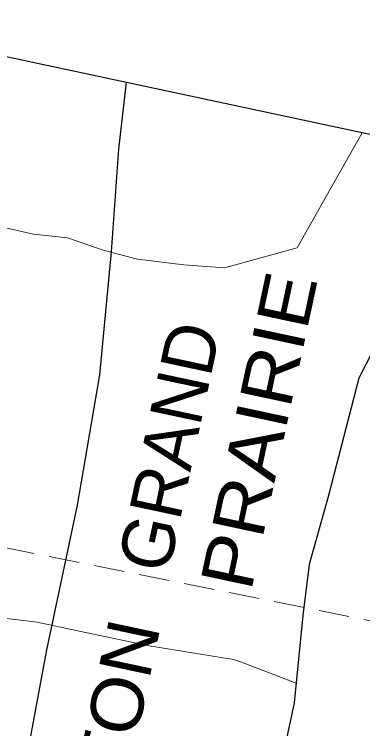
# Model space of a CAD drawing. Extents: x 2363411 to 2369126, y 6976878 to 6988319.
# Drawn here: x 2365979.2 to 2366047.6, y 6977238.8 to 6977379 of the extents above; entities that cross this region are included whole.
import ezdxf

# ---------------------------------------------------------------- set-up
doc = ezdxf.new("R2010")
doc.units = 0
doc.header["$LTSCALE"] = 2
doc.linetypes.add('MEDIUM_DASHED', pattern=[4.5, 3, -1.5])
doc.layers.add('62', color=7, linetype='Continuous', lineweight=13)
doc.layers.add('63', color=7, linetype='Continuous', lineweight=13)

msp = doc.modelspace()

# ---------------------------------------------------------------- linework, layer by layer
at = {"layer": '62', "linetype": 'MEDIUM_DASHED'}
msp.add_line((2365844.834, 6977300.827), (2366120.392, 6977245.768), dxfattribs=at)
at = {"layer": '62'}
for p, q in [((2365983.687, 6977259.747), (2365971.313, 6977261.17)), ((2366022.198, 6977252.394), (2366023.784, 6977251.848)), ((2366023.784, 6977251.848), (2366034.504, 6977247.738))]:
    msp.add_line(p, q, dxfattribs=at)
at = {"layer": '62', "lineweight": 25}
for points in [[(2365678.211, 6976974.92), (2366133.213, 6976877.7), (2366227.156, 6977317.368), (2365772.152, 6977414.588)], [(2366001.163, 6977365.655), (2365999.671, 6977352.535), (2365998.241, 6977332.387), (2365995.964, 6977308.275), (2365991.577, 6977282.681), (2365985.507, 6977254.272), (2365979.695, 6977222.865), (2365976.994, 6977204.85)], [(2366071.953, 6977350.532), (2366062.056, 6977339.206), (2366054.911, 6977323.43), (2366046.839, 6977307.62), (2366040.832, 6977284.562), (2366037.039, 6977271.012), (2366035.805, 6977261.035), (2366034.117, 6977243.885), (2366031.631, 6977232.244), (2366030.337, 6977223.387)]]:
    msp.add_lwpolyline(points, dxfattribs=at)
at = {"layer": '62'}
for points in [[(2366047.44, 6977355.767), (2366042.741, 6977347.452), (2366034.74, 6977333.17), (2366020.483, 6977329.222), (2366012.499, 6977329.869), (2366003.367, 6977330.969), (2365996.823, 6977332.643), (2365989.672, 6977335.137), (2365982.964, 6977335.834), (2365973.973, 6977337.918)], [(2365983.687, 6977259.747), (2365993.192, 6977257.714), (2366005.671, 6977255.05), (2366022.198, 6977252.394)]]:
    msp.add_lwpolyline(points, dxfattribs=at)
at = {"layer": '63', "linetype": 'MEDIUM_DASHED'}
msp.add_line((2365844.834, 6977300.827), (2366120.392, 6977245.768), dxfattribs=at)
at = {"layer": '63'}
for p, q in [((2365983.687, 6977259.747), (2365971.313, 6977261.17)), ((2366022.198, 6977252.394), (2366023.784, 6977251.848)), ((2366023.784, 6977251.848), (2366034.504, 6977247.738))]:
    msp.add_line(p, q, dxfattribs=at)
at = {"layer": '63', "lineweight": 25}
for points in [[(2365678.211, 6976974.92), (2366133.213, 6976877.7), (2366227.156, 6977317.368), (2365772.152, 6977414.588)], [(2366001.163, 6977365.655), (2365999.671, 6977352.535), (2365998.241, 6977332.387), (2365995.964, 6977308.275), (2365991.577, 6977282.681), (2365985.507, 6977254.272), (2365979.695, 6977222.865), (2365976.994, 6977204.85)], [(2366071.953, 6977350.532), (2366062.056, 6977339.206), (2366054.911, 6977323.43), (2366046.839, 6977307.62), (2366040.832, 6977284.562), (2366037.039, 6977271.012), (2366035.805, 6977261.035), (2366034.117, 6977243.885), (2366031.631, 6977232.244), (2366030.337, 6977223.387)]]:
    msp.add_lwpolyline(points, dxfattribs=at)
at = {"layer": '63'}
for points in [[(2366047.44, 6977355.767), (2366042.741, 6977347.452), (2366034.74, 6977333.17), (2366020.483, 6977329.222), (2366012.499, 6977329.869), (2366003.367, 6977330.969), (2365996.823, 6977332.643), (2365989.672, 6977335.137), (2365982.964, 6977335.834), (2365973.973, 6977337.918)], [(2365983.687, 6977259.747), (2365993.192, 6977257.714), (2366005.671, 6977255.05), (2366022.198, 6977252.394)]]:
    msp.add_lwpolyline(points, dxfattribs=at)

# ---------------------------------------------------------------- texts
at = {"layer": '62'}
for s, width, p in [('PRAIRIE', 1.15, (2366025.65, 6977265.53)), ('ARLINGTON', 1.1, (2365989.614, 6977173.114))]:
    msp.add_text(s, height=10.21, rotation=77.939, dxfattribs=dict(at, width=width)).set_placement(p)
msp.add_text('GRAND', height=10.21, rotation=77.939, dxfattribs=at).set_placement((2366009.455, 6977268.991))
at = {"layer": '63'}
for s, width, p in [('PRAIRIE', 1.15, (2366025.65, 6977265.53)), ('ARLINGTON', 1.1, (2365989.614, 6977173.114))]:
    msp.add_text(s, height=10.21, rotation=77.939, dxfattribs=dict(at, width=width)).set_placement(p)
msp.add_text('GRAND', height=10.21, rotation=77.939, dxfattribs=at).set_placement((2366009.455, 6977268.991))

doc.saveas('drawing.dxf')
